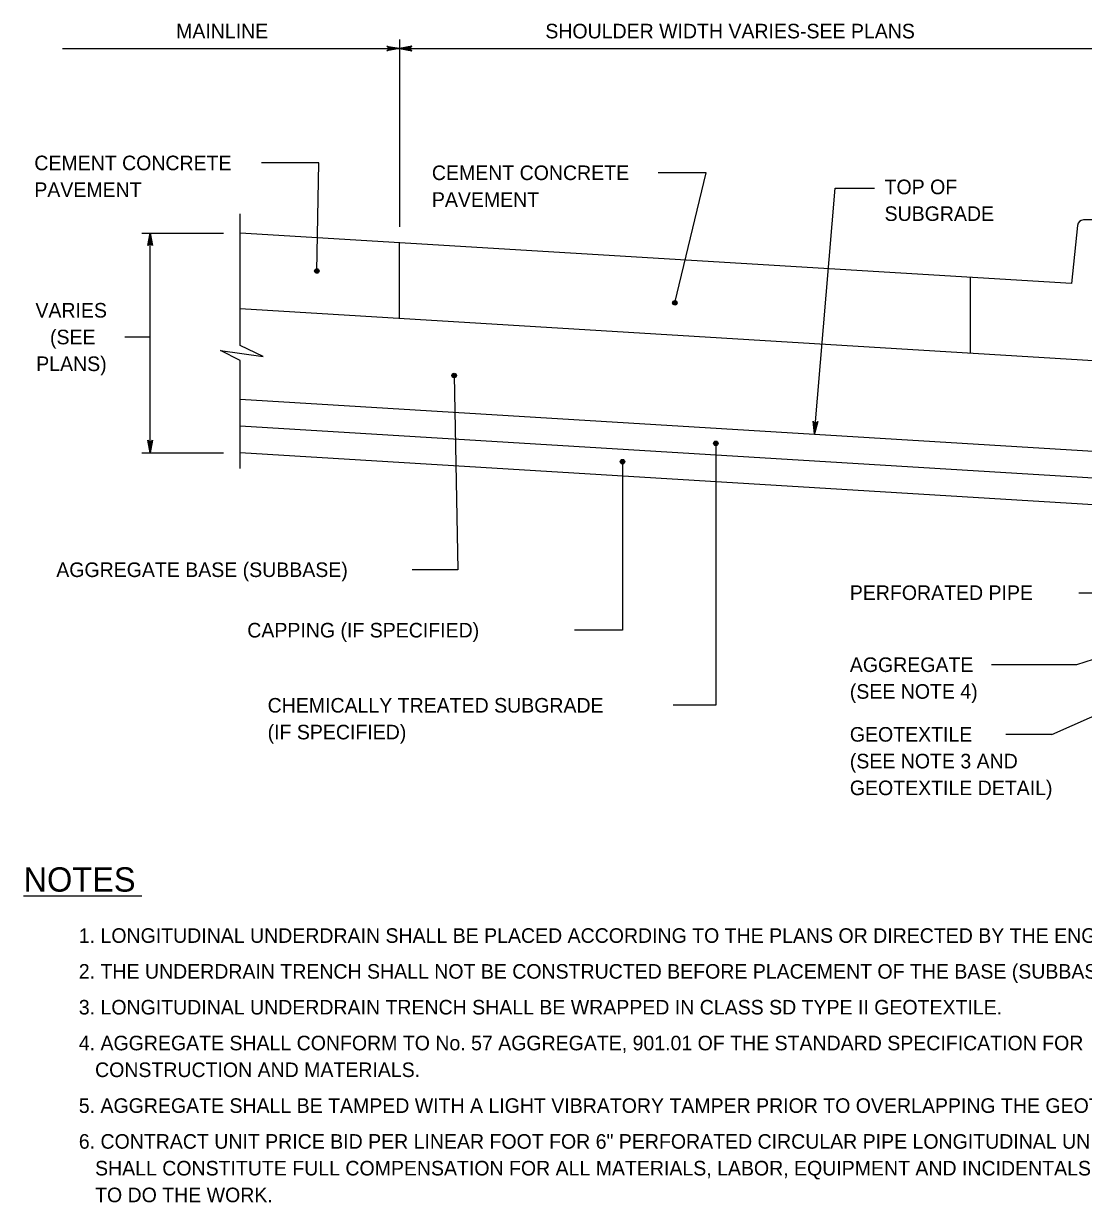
# Model space of a CAD drawing. Extents: x -0.97 to 5.98, y -2.63 to 7.27.
# Drawn here: x -0.972 to 3.389, y 2.423 to 7.27 of the extents above; entities that cross this region are included whole.
import ezdxf

# ---------------------------------------------------------------- set-up
doc = ezdxf.new("R2010")
doc.units = 0
for name, color, linetype in [('DETL-DIMS', 7, 'Continuous'), ('DETL-LINE', 7, 'Continuous'), ('DETL-NOTE', 7, 'Continuous')]:
    doc.layers.add(name, color=color, linetype=linetype)

msp = doc.modelspace()

# ---------------------------------------------------------------- linework, layer by layer
at = {"layer": 'DETL-DIMS'}
for p, q in [((0.5745, 7.2048), (0.5745, 6.4344)), ((-0.8117, 7.1678), (5.0884, 7.1678)), ((0.2426, 6.6973), (0.0072, 6.6973)), ((0.2351, 6.2528), (0.2426, 6.6973)), ((1.8361, 6.6568), (1.6397, 6.6568)), ((1.7081, 6.1219), (1.8361, 6.6568)), ((2.2818, 5.5834), (2.3674, 6.5942)), ((2.3674, 6.5942), (2.529, 6.5942)), ((-0.4845, 6.4092), (-0.1496, 6.4092)), ((-0.4512, 5.5053), (-0.4512, 6.4092)), ((-0.4512, 5.9815), (-0.5556, 5.9815)), ((0.7998, 5.8233), (0.8148, 5.0247)), ((1.8765, 5.5446), (1.8765, 4.4672)), ((-0.4845, 5.5053), (-0.1496, 5.5053)), ((1.4925, 5.4692), (1.4925, 4.7761)), ((0.8148, 5.0247), (0.6265, 5.0247)), ((3.3702, 4.9303), (4.0534, 4.9303)), ((3.8868, 4.8034), (3.36, 4.6342)), ((1.4925, 4.7761), (1.2955, 4.7761)), ((3.36, 4.6342), (3.01, 4.6342)), ((3.2591, 4.3478), (3.8673, 4.6179)), ((1.8765, 4.4672), (1.7008, 4.4672)), ((3.2591, 4.3478), (3.0698, 4.3478))]:
    msp.add_line(p, q, dxfattribs=at)
for points in [[(0.5745, 7.1678), (0.5228, 7.1581), (0.5267, 7.1608), (0.5288, 7.1643), (0.5294, 7.1678), (0.5288, 7.1713), (0.5267, 7.1747), (0.5228, 7.1775), (0.5745, 7.1678), (0.5267, 7.1747), (0.5288, 7.1713), (0.5745, 7.1678), (0.5294, 7.1678), (0.5288, 7.1643), (0.5745, 7.1678), (0.5267, 7.1608)], [(0.5745, 7.1678), (0.6263, 7.1775), (0.6223, 7.1747), (0.6203, 7.1713), (0.6197, 7.1678), (0.6203, 7.1643), (0.6223, 7.1608), (0.6263, 7.1581), (0.5745, 7.1678), (0.6223, 7.1608), (0.6203, 7.1643), (0.5745, 7.1678), (0.6197, 7.1678), (0.6203, 7.1713), (0.5745, 7.1678), (0.6223, 7.1747)], [(0.5745, 7.1678), (0.6263, 7.1581), (0.6223, 7.1608), (0.6203, 7.1643), (0.6197, 7.1678), (0.6203, 7.1713), (0.6223, 7.1747), (0.6263, 7.1775), (0.5745, 7.1678), (0.6223, 7.1747), (0.6203, 7.1713), (0.5745, 7.1678), (0.6197, 7.1678), (0.6203, 7.1643), (0.5745, 7.1678), (0.6223, 7.1608)], [(-0.4512, 6.4092), (-0.4415, 6.3574), (-0.4442, 6.3614), (-0.4477, 6.3634), (-0.4512, 6.364), (-0.4547, 6.3634), (-0.4581, 6.3614), (-0.4609, 6.3574), (-0.4512, 6.4092), (-0.4581, 6.3614), (-0.4547, 6.3634), (-0.4512, 6.4092), (-0.4512, 6.364), (-0.4477, 6.3634), (-0.4512, 6.4092), (-0.4442, 6.3614)], [(2.2818, 5.5834), (2.2765, 5.6359), (2.2789, 5.6316), (2.2822, 5.6293), (2.2856, 5.6284), (2.2891, 5.6287), (2.2928, 5.6305), (2.2959, 5.6342), (2.2818, 5.5834), (2.2928, 5.6305), (2.2891, 5.6287), (2.2818, 5.5834), (2.2856, 5.6284), (2.2822, 5.6293), (2.2818, 5.5834), (2.2789, 5.6316)], [(-0.4512, 5.5053), (-0.4609, 5.5571), (-0.4581, 5.5531), (-0.4547, 5.5511), (-0.4512, 5.5505), (-0.4477, 5.5511), (-0.4442, 5.5531), (-0.4415, 5.5571), (-0.4512, 5.5053), (-0.4442, 5.5531), (-0.4477, 5.5511), (-0.4512, 5.5053), (-0.4512, 5.5505), (-0.4547, 5.5511), (-0.4512, 5.5053), (-0.4581, 5.5531)]]:
    msp.add_lwpolyline(points, dxfattribs=at)
for centre, radius in [((0.2351, 6.2528), 0.00926), ((0.2351, 6.2528), 0.00694), ((0.2351, 6.2528), 0.00463), ((0.2351, 6.2528), 0.00231), ((1.7081, 6.1219), 0.00926), ((1.7081, 6.1219), 0.00694), ((1.7081, 6.1219), 0.00463), ((1.7081, 6.1219), 0.00231), ((0.7998, 5.8233), 0.00926), ((0.7998, 5.8233), 0.00694), ((0.7998, 5.8233), 0.00463), ((0.7998, 5.8233), 0.00231), ((1.8765, 5.5446), 0.00926), ((1.8765, 5.5446), 0.00694), ((1.8765, 5.5446), 0.00463), ((1.8765, 5.5446), 0.00231), ((1.4925, 5.4692), 0.00926), ((1.4925, 5.4692), 0.00694), ((1.4925, 5.4692), 0.00463), ((1.4925, 5.4692), 0.00231)]:
    msp.add_circle(centre, radius, dxfattribs=at)
at = {"layer": 'DETL-LINE'}
for p, q in [((-0.0802, 5.9466), (-0.0802, 6.4883)), ((3.5162, 6.4628), (3.3888, 6.4628)), ((3.3399, 6.2016), (-0.0802, 6.4092)), ((3.3639, 6.4403), (3.3399, 6.2016)), ((0.5745, 6.0572), (0.5745, 6.3692)), ((2.9242, 5.9138), (2.9242, 6.2268)), ((3.8687, 5.8562), (-0.0802, 6.0971)), ((-0.0802, 5.4408), (-0.0802, 5.8856)), ((3.8687, 5.4834), (-0.0802, 5.7244)), ((3.8687, 5.3739), (-0.0802, 5.6149)), ((3.8687, 5.2644), (-0.0802, 5.5053)), ((-0.9716, 3.684), (-0.4844, 3.684))]:
    msp.add_line(p, q, dxfattribs=at)
msp.add_lwpolyline([(-0.0802, 5.8856), (-0.1618, 5.9256), (0.0144, 5.9016), (-0.0802, 5.9466)], dxfattribs=at)
msp.add_arc((3.3888, 6.4378), 0.025, 90, 174.2625, dxfattribs=at)

# ---------------------------------------------------------------- texts
at = {"layer": 'DETL-NOTE'}
for s, height, p in [('MAINLINE', 0.06, (-0.344, 7.2094)), ('SHOULDER WIDTH VARIES-SEE PLANS', 0.06, (1.175, 7.2094)), ('CEMENT CONCRETE', 0.06, (-0.9273, 6.6673)), ('CEMENT CONCRETE', 0.06, (0.7083, 6.6268)), ('PAVEMENT', 0.06, (-0.9273, 6.5573)), ('TOP OF', 0.06, (2.5707, 6.5688)), ('PAVEMENT', 0.06, (0.7083, 6.5168)), ('SUBGRADE', 0.06, (2.5707, 6.4588)), ('VARIES', 0.06, (-0.9228, 6.0615)), ('(SEE', 0.06, (-0.8628, 5.9515)), ('PLANS)', 0.06, (-0.9196, 5.8415)), ('AGGREGATE BASE (SUBBASE)', 0.06, (-0.837, 4.9947)), ('PERFORATED PIPE', 0.06, (2.4277, 4.9003)), ('CAPPING (IF SPECIFIED)', 0.06, (-0.0512, 4.7461)), ('AGGREGATE', 0.06, (2.4277, 4.6042)), ('(SEE NOTE 4)', 0.06, (2.4277, 4.4942)), ('CHEMICALLY TREATED SUBGRADE', 0.06, (0.0325, 4.4372)), ('(IF SPECIFIED)', 0.06, (0.0325, 4.3272)), ('GEOTEXTILE', 0.06, (2.4277, 4.3178)), ('(SEE NOTE 3 AND', 0.06, (2.4277, 4.2078)), ('GEOTEXTILE DETAIL)', 0.06, (2.4277, 4.0978)), ('NOTES', 0.1, (-0.9716, 3.7011)), ('1. LONGITUDINAL UNDERDRAIN SHALL BE PLACED ACCORDING TO THE PLANS OR DIRECTED BY THE ENGINEER.', 0.06, (-0.7443, 3.4905)), ('2. THE UNDERDRAIN TRENCH SHALL NOT BE CONSTRUCTED BEFORE PLACEMENT OF THE BASE (SUBBASE) COURSE.', 0.06, (-0.7443, 3.3432)), ('3. LONGITUDINAL UNDERDRAIN TRENCH SHALL BE WRAPPED IN CLASS SD TYPE II GEOTEXTILE.', 0.06, (-0.7443, 3.1959)), ('4. AGGREGATE SHALL CONFORM TO No. 57 AGGREGATE, 901.01 OF THE STANDARD SPECIFICATION FOR ', 0.06, (-0.7443, 3.0486)), ('   CONSTRUCTION AND MATERIALS.', 0.06, (-0.7443, 2.9386)), ('5. AGGREGATE SHALL BE TAMPED WITH A LIGHT VIBRATORY TAMPER PRIOR TO OVERLAPPING THE GEOTEXTILE FABRIC.', 0.06, (-0.7443, 2.7913)), ('6. CONTRACT UNIT PRICE BID PER LINEAR FOOT FOR 6" PERFORATED CIRCULAR PIPE LONGITUDINAL UNDERDRAIN ', 0.06, (-0.7443, 2.644)), ('   SHALL CONSTITUTE FULL COMPENSATION FOR ALL MATERIALS, LABOR, EQUIPMENT AND INCIDENTALS NECESSARY ', 0.06, (-0.7443, 2.534)), ('   TO DO THE WORK.', 0.06, (-0.7443, 2.424))]:
    msp.add_text(s, height=height, dxfattribs=at).set_placement(p)

doc.saveas('drawing.dxf')
